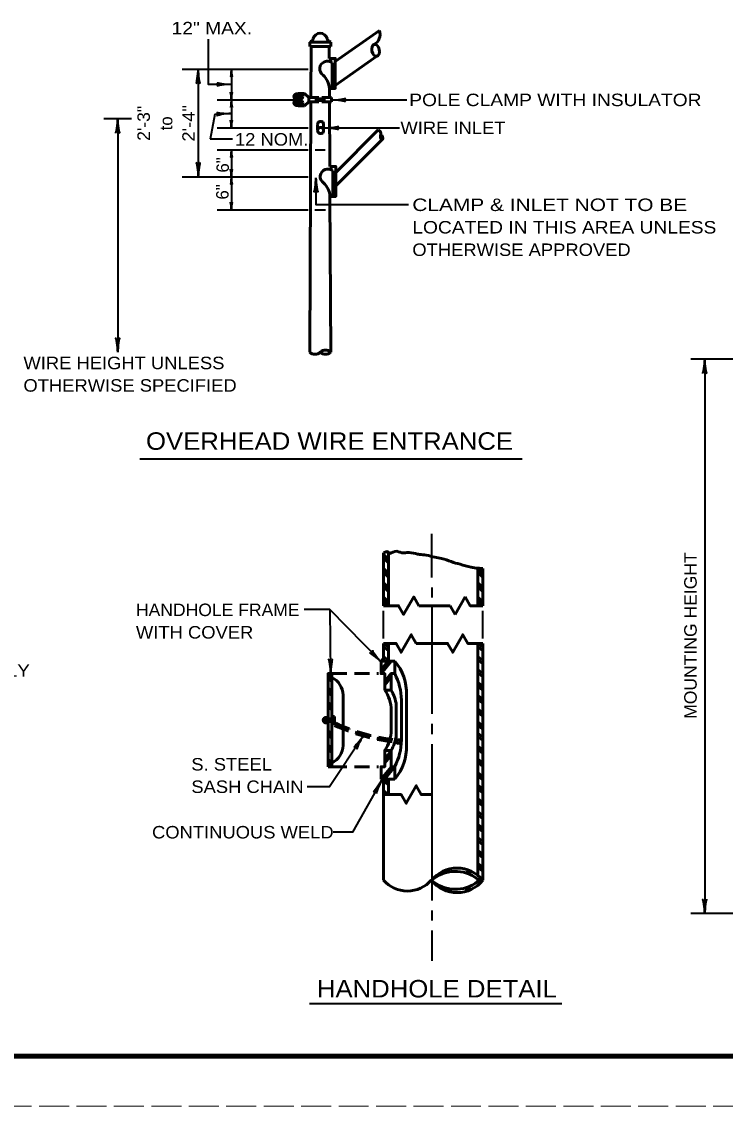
# Model space of a CAD drawing. Extents: x -1 to 679, y 1 to 441.
# Drawn here: x 219.9 to 360.8, y 0.8 to 218 of the extents above; entities that cross this region are included whole.
import ezdxf
from ezdxf.enums import TextEntityAlignment as Align

# ---------------------------------------------------------------- set-up
doc = ezdxf.new("R2010")
doc.units = 0
doc.linetypes.add('LONG_DASHED', pattern=[7.5, 6, -1.5])
doc.linetypes.add('MEDIUM_DASHED', pattern=[4.5, 3, -1.5])
doc.layers.add('1', color=7, linetype='Continuous', lineweight=13)
doc.layers.add('61', color=7, linetype='Continuous', lineweight=35)

msp = doc.modelspace()

# ---------------------------------------------------------------- hatches: boundary and pattern name
at = {"layer": '1'}
h = msp.add_hatch(color=256, dxfattribs=at)
edge = h.paths.add_edge_path()
edge.add_ellipse((275.324, 202.986), major_axis=(0.9, 0), ratio=0.6666667, start_angle=0, end_angle=360)
h = msp.add_hatch(color=256, dxfattribs=at)
edge = h.paths.add_edge_path()
edge.add_ellipse((275.324, 201.743), major_axis=(0.9, 0), ratio=0.6666667, start_angle=0, end_angle=360)
msp.add_hatch(color=256, dxfattribs=at).paths.add_polyline_path([(281.383, 78.137, 1), (280.293, 78.137, 1)])

# ---------------------------------------------------------------- linework, layer by layer
at = {"layer": '1', "lineweight": 53}
for p, q in [((282.705, 210.014), (291.552, 216.209)), ((277.594, 213.914), (281.794, 213.914)), ((277.594, 213.914), (277.594, 213.014)), ((277.594, 213.014), (281.794, 213.014)), ((277.894, 213.014), (277.844, 202.814)), ((281.494, 213.014), (281.505, 210.614)), ((281.794, 213.914), (281.794, 213.014)), ((282.705, 205.214), (291.061, 211.065)), ((281.805, 210.614), (281.805, 209.915)), ((282.105, 209.714), (282.105, 204.614)), ((281.535, 204.614), (281.543, 202.814)), ((276.524, 203.585), (275.324, 203.585)), ((277.444, 202.814), (276.524, 203.585)), ((277.444, 202.814), (279.394, 202.814)), ((277.444, 202.814), (277.444, 201.914)), ((278.914, 202.814), (278.914, 201.914)), ((279.394, 202.814), (279.394, 201.914)), ((279.994, 202.814), (281.944, 202.814)), ((279.994, 202.814), (279.994, 201.914)), ((280.474, 202.814), (280.474, 201.914)), ((281.944, 202.814), (281.944, 201.914)), ((276.524, 201.143), (275.324, 201.143)), ((277.444, 201.914), (276.524, 201.143)), ((277.444, 201.914), (279.394, 201.914)), ((277.839, 201.914), (277.594, 151.814)), ((279.994, 201.914), (281.944, 201.914)), ((281.548, 201.914), (281.611, 189.014)), ((279.17, 197.402), (279.176, 196.202)), ((280.37, 197.408), (280.376, 196.208)), ((282.811, 187.814), (291.297, 196.3)), ((282.811, 185.114), (292.145, 194.448)), ((281.911, 189.014), (281.911, 188.315)), ((282.211, 188.114), (282.211, 183.014)), ((281.641, 183.014), (281.794, 151.814)), ((292.372, 101.052), (292.372, 111.652)), ((293.372, 110.332), (292.372, 111.332)), ((293.372, 101.052), (293.372, 111.652)), ((293.372, 109.612), (292.372, 110.612)), ((293.372, 107.472), (292.372, 108.472)), ((293.372, 106.752), (292.372, 107.772)), ((311.272, 101.052), (311.272, 108.472)), ((312.272, 107.472), (311.272, 108.472)), ((312.272, 106.752), (311.272, 107.772)), ((312.272, 101.052), (312.272, 108.472)), ((293.372, 104.632), (292.372, 105.632)), ((293.372, 103.912), (292.372, 104.912)), ((312.272, 104.632), (311.272, 105.632)), ((312.272, 103.912), (311.272, 104.912)), ((293.372, 101.772), (292.372, 102.772)), ((293.372, 101.052), (292.372, 102.072)), ((308.752, 102.812), (306.732, 99.312)), ((312.272, 101.772), (311.272, 102.772)), ((312.272, 101.052), (311.272, 102.072)), ((299.432, 101.052), (305.732, 101.052)), ((306.732, 99.312), (305.732, 101.052)), ((292.372, 93.492), (293.372, 92.672)), ((292.372, 93.492), (292.372, 89.972)), ((293.372, 93.492), (293.372, 89.972)), ((311.272, 93.492), (312.272, 92.672)), ((312.272, 93.492), (312.272, 46.132)), ((292.372, 92.852), (293.372, 92.012)), ((311.272, 92.852), (312.272, 92.012)), ((293.872, 89.972), (291.872, 87.452)), ((293.232, 89.972), (291.872, 88.252)), ((291.872, 89.972), (293.872, 89.972)), ((292.372, 90.892), (293.372, 90.052)), ((292.372, 90.232), (292.692, 89.972)), ((294.632, 89.972), (292.612, 89.972)), ((311.272, 90.892), (312.272, 90.052)), ((311.272, 90.232), (312.272, 89.412)), ((282.032, 86.612), (281.272, 87.372)), ((282.032, 68.812), (282.032, 87.452)), ((293.872, 87.552), (292.612, 85.972)), ((311.272, 88.272), (312.272, 87.452)), ((311.272, 87.612), (312.272, 86.792)), ((282.032, 85.912), (281.272, 86.672)), ((293.872, 86.752), (292.612, 85.172)), ((311.272, 85.652), (312.272, 84.832)), ((311.272, 85.012), (312.272, 84.172)), ((282.032, 83.772), (281.272, 84.532)), ((282.032, 83.052), (281.272, 83.812)), ((284.312, 83.172), (284.312, 73.092)), ((293.872, 84.172), (292.612, 84.172)), ((296.952, 73.092), (296.952, 83.172)), ((311.272, 83.052), (312.272, 82.212)), ((282.032, 80.912), (281.272, 81.672)), ((282.032, 80.212), (281.272, 80.972)), ((294.932, 75.112), (294.932, 81.152)), ((295.952, 74.092), (295.952, 82.152)), ((311.272, 82.392), (312.272, 81.572)), ((311.272, 80.432), (312.272, 79.612)), ((282.032, 78.372), (281.272, 78.372)), ((282.032, 78.252), (281.272, 78.252)), ((282.532, 78.892), (282.032, 78.892)), ((282.152, 78.892), (282.152, 77.372)), ((282.232, 78.892), (282.232, 77.372)), ((282.232, 78.892), (282.232, 77.372)), ((282.312, 78.892), (282.312, 77.372)), ((282.312, 78.892), (282.312, 77.372)), ((282.372, 78.892), (282.372, 77.372)), ((282.432, 78.892), (282.432, 77.372)), ((282.452, 78.892), (282.452, 77.372)), ((282.492, 78.892), (282.492, 77.372)), ((282.532, 78.892), (282.532, 77.372)), ((293.932, 76.112), (293.932, 80.152)), ((311.272, 79.792), (312.272, 78.952)), ((282.032, 78.172), (281.272, 78.172)), ((282.032, 78.172), (281.272, 78.172)), ((282.032, 78.052), (281.272, 78.052)), ((282.032, 77.932), (281.272, 77.932)), ((282.032, 77.872), (281.272, 77.872)), ((282.532, 77.372), (282.032, 77.372)), ((311.272, 77.832), (312.272, 76.992)), ((311.272, 77.172), (312.272, 76.332)), ((282.032, 75.212), (281.272, 75.972)), ((282.032, 74.512), (281.272, 75.252)), ((311.272, 75.532), (312.272, 74.712)), ((311.272, 74.892), (312.272, 74.052)), ((282.032, 72.372), (281.272, 73.132)), ((282.032, 71.652), (281.272, 72.412)), ((293.872, 71.952), (292.612, 70.372)), ((311.272, 72.932), (312.272, 72.092)), ((311.272, 72.272), (312.272, 71.452)), ((282.032, 69.512), (281.272, 70.272)), ((282.032, 68.812), (281.272, 69.552)), ((293.872, 71.132), (292.612, 69.572)), ((311.272, 70.312), (312.272, 69.492)), ((311.272, 69.652), (312.272, 68.832)), ((282.032, 68.812), (281.272, 68.812)), ((293.952, 68.812), (291.932, 66.292)), ((294.632, 68.852), (292.572, 66.292)), ((311.272, 67.692), (312.272, 66.872)), ((291.872, 66.292), (293.872, 66.292)), ((292.372, 66.292), (292.372, 63.252)), ((292.372, 66.032), (293.372, 65.192)), ((294.632, 66.292), (292.612, 66.292)), ((292.852, 66.292), (293.372, 65.852)), ((293.372, 66.292), (293.372, 63.252)), ((311.272, 67.052), (312.272, 66.212)), ((292.372, 64.072), (293.352, 63.252)), ((292.372, 63.412), (292.552, 63.252)), ((311.272, 65.092), (312.272, 64.252)), ((311.272, 64.432), (312.272, 63.612)), ((311.272, 62.472), (312.272, 61.652)), ((311.272, 61.832), (312.272, 60.992)), ((311.272, 59.872), (312.272, 59.032)), ((311.272, 59.212), (312.272, 58.372)), ((311.272, 57.252), (312.272, 56.412)), ((311.272, 56.592), (312.272, 55.772)), ((311.272, 54.632), (312.272, 53.812)), ((311.272, 53.992), (312.272, 53.152)), ((311.272, 52.032), (312.272, 51.192)), ((311.272, 51.372), (312.272, 50.552)), ((304.732, 48.072), (304.932, 47.632)), ((305.212, 48.232), (305.432, 47.732)), ((309.312, 48.132), (309.012, 47.492)), ((309.772, 47.952), (309.492, 47.312)), ((311.272, 49.412), (312.272, 48.592)), ((311.272, 48.752), (312.272, 47.932)), ((310.972, 45.652), (312.152, 45.972)), ((311.272, 46.252), (311.912, 46.432)), ((304.912, 43.992), (305.132, 44.452)), ((305.392, 43.852), (305.632, 44.372)), ((309.132, 43.932), (308.832, 44.592)), ((309.612, 44.112), (309.312, 44.752))]:
    msp.add_line(p, q, dxfattribs=at)
at = {"layer": '1', "lineweight": 35}
for p, q in [((252.054, 208.483), (277.272, 208.483)), ((255.256, 208.483), (255.256, 186.92)), ((259.054, 202.352), (274.389, 202.352)), ((281.944, 202.334), (297.022, 202.334)), ((241.889, 198.562), (236.389, 198.562)), ((239.139, 198.562), (239.139, 151.814)), ((258.577, 199.455), (257.684, 194.482)), ((258.577, 199.455), (261.816, 199.613)), ((259.054, 196.75), (277.272, 196.75)), ((280.509, 196.72), (295.587, 196.72)), ((262.119, 194.482), (257.684, 194.482)), ((259.054, 192.311), (277.272, 192.311)), ((278.692, 192.314), (280.695, 192.314)), ((252.054, 186.92), (277.272, 186.92)), ((259.054, 180.312), (277.272, 180.312)), ((278.633, 180.314), (280.754, 180.314)), ((372.357, 150.421), (353.908, 150.421)), ((356.689, 150.421), (356.689, 39.421)), ((302.072, 106.692), (302.072, 115.432)), ((302.072, 104.692), (302.072, 102.672)), ((281.628, 100.328), (276.504, 100.328)), ((292.372, 94.512), (292.372, 100.052)), ((302.072, 101.052), (302.072, 97.292)), ((302.072, 100.652), (302.072, 79.392)), ((312.272, 94.512), (312.272, 100.052)), ((302.072, 77.372), (302.072, 75.352)), ((302.072, 73.332), (302.072, 42.052)), ((302.072, 40.032), (302.072, 38.012)), ((372.357, 39.421), (353.908, 39.421)), ((302.072, 36.012), (302.072, 29.972))]:
    msp.add_line(p, q, dxfattribs=at)
at = {"layer": '1', "lineweight": 40}
for p, q in [((243.596, 130.453), (320.124, 130.453)), ((277.557, 21.378), (328.11, 21.378))]:
    msp.add_line(p, q, dxfattribs=at)
at = {"layer": '1', "linetype": 'MEDIUM_DASHED', "lineweight": 53}
for p, q in [((282.032, 87.452), (291.352, 87.452)), ((282.032, 68.812), (291.352, 68.812))]:
    msp.add_line(p, q, dxfattribs=at)
at = {"layer": '1', "lineweight": 35}
for points in [[(261.854, 205.417), (257.318, 205.417), (257.318, 214.491)], [(261.916, 208.483), (261.916, 202.352), (261.916, 196.75)], [(261.916, 192.311), (261.916, 186.92), (261.916, 180.312)], [(278.837, 186.709), (278.837, 181.415), (297.384, 181.415)], [(291.872, 89.8), (281.628, 100.328), (281.782, 87.452)], [(288.311, 74.955), (281.544, 64.773), (277.072, 64.773)], [(292.015, 66.149), (286.186, 55.713), (282.28, 55.713)]]:
    msp.add_lwpolyline(points, dxfattribs=at)
at = {"layer": '1', "lineweight": 53}
for points in [[(281.505, 210.614), (282.705, 210.614), (282.705, 204.614), (281.535, 204.614)], [(281.611, 189.014), (282.811, 189.014), (282.811, 183.014), (281.641, 183.014)], [(292.372, 101.052), (295.392, 101.052), (296.392, 99.312), (298.412, 102.812), (299.432, 101.052)], [(312.272, 101.052), (309.752, 101.052), (308.752, 102.812)], [(292.372, 93.492), (294.892, 93.492), (295.892, 91.752), (297.912, 95.252), (298.912, 93.492)], [(312.272, 93.492), (309.252, 93.492), (308.252, 95.252), (306.232, 91.752), (305.212, 93.492), (298.912, 93.492)], [(311.272, 93.492), (311.272, 73.052), (311.272, 47.032)], [(292.612, 84.172), (292.612, 87.452), (291.872, 87.452), (291.872, 89.972)], [(292.612, 84.172), (293.872, 84.172), (293.872, 87.452), (294.632, 87.452), (294.632, 89.972)], [(281.272, 68.812), (281.272, 87.452), (282.032, 87.452)], [(293.872, 72.072), (292.612, 72.072), (292.612, 68.812), (291.872, 68.812), (291.872, 66.292)], [(292.612, 72.072), (293.872, 72.072), (293.872, 68.812), (294.632, 68.812), (294.632, 66.292)], [(301.952, 63.252), (299.932, 63.252), (298.912, 65.012), (296.912, 61.512), (295.892, 63.252), (292.372, 63.252), (292.372, 46.132)]]:
    msp.add_lwpolyline(points, dxfattribs=at)
for points in [[(291.872, 89.972), (292.372, 90.472), (292.372, 89.972)], [(291.872, 66.292), (292.372, 65.792), (292.372, 66.292)]]:
    msp.add_lwpolyline(points, close=True, dxfattribs=at)
for centre, radius in [((280.838, 78.137), 0.545), ((295.359, 73.854), 0.378)]:
    msp.add_circle(centre, radius, dxfattribs=at)
for centre, radius, start, end in [((279.694, 214.226), 1.442, 16.19781, 163.80219), ((289.443, 215.437), 2.246, 295.32486, 20.09191), ((277.402, 214.822), 0.928, 281.94387, 347.91984), ((281.986, 214.822), 0.928, 192.08016, 258.05613), ((281.114, 208.558), 1.523, 49.39069, 236.15933), ((277.59, 204.387), 3.951, 3.29768, 47.3671), ((279.77, 197.42), 0.6, 358.85054, 181.71286), ((279.776, 196.22), 0.6, 358.85054, 181.71286), ((279.776, 196.184), 0.6, 178.28714, 1.14946), ((291.012, 195.509), 0.84, 339.80476, 70.23541), ((281.22, 186.958), 1.523, 49.39069, 236.15933), ((277.696, 182.787), 3.951, 3.29768, 47.3671), ((280.744, 150.722), 1.515, 46.13132, 133.86867), ((278.644, 152.907), 1.515, 226.13132, 313.86868), ((280.744, 152.907), 1.515, 226.13132, 313.86868), ((287.236, 83.654), 9.729, 357.13004, 40.48815), ((284.139, 82.045), 11.806, 0.54939, 27.24732), ((280.2, 83.021), 4.106, 2.02606, 63.44439), ((286.947, 80.104), 6.982, 0.31998, 35.66459), ((287.801, 80.352), 7.18, 6.38376, 32.16514), ((286.947, 76.15), 6.982, 324.33541, 359.68002), ((287.801, 75.901), 7.18, 327.83486, 353.61624), ((284.139, 74.243), 11.806, 332.75268, 359.45061), ((280.2, 73.232), 4.106, 296.55561, 357.97394), ((287.236, 72.635), 9.729, 319.51185, 2.86996), ((306.751, 40.681), 7.178, 51.54154, 132.04732), ((307.109, 41.942), 6.576, 38.8447, 141.1553), ((297.155, 50.243), 6.317, 220.71167, 319.28832), ((307.109, 50.191), 6.576, 218.22248, 321.77751), ((306.751, 51.453), 7.178, 227.95268, 308.4983), ((311.038, 46.068), 0.294, 307.8273, 52.77092)]:
    msp.add_arc(centre, radius, start, end, dxfattribs=at)
at = {"layer": '1', "linetype": 'MEDIUM_DASHED', "lineweight": 53}
for centre, radius, start, end in [((299.23, 113.296), 39.613, 245.08086, 263.60629), ((298.714, 111.75), 38.237, 245.04728, 263.19799), ((298.378, 110.55), 36.501, 244.77769, 263.49597)]:
    msp.add_arc(centre, radius, start, end, dxfattribs=at)
at = {"layer": '1', "lineweight": 53}
for centre, major_axis, ratio in [((290.793, 212.251), (-0.268, 1.186), 0.618585), ((275.324, 202.986), (0.9, 0), 0.666667), ((275.324, 201.743), (0.9, 0), 0.666667), ((291.986, 194.838), (-0.159, 0.39), 0.505648)]:
    msp.add_ellipse(centre, major_axis=major_axis, ratio=ratio, dxfattribs=at)
at = {"layer": '1', "lineweight": 40}
for centre, major_axis, ratio, start_param, end_param in [((255.044, 207.353), (0.176, 1.756), 0.07063, 3.1407148, 5.41811), ((255.532, 207.383), (-0.156, 1.786), 0.122415, 0.8963533, 3.1415927), ((261.708, 207.353), (0.176, 1.756), 0.07063, 4.7093373, 5.41811), ((262.196, 207.382), (-0.156, 1.786), 0.122415, 0.8963533, 1.5837952), ((261.888, 208.7), (0.176, 1.756), 0.07063, 3.1407148, 3.8293255), ((262, 208.72), (-0.156, 1.786), 0.122415, 2.4431075, 3.1415927), ((260.763, 205.14), (1.786, 0.156), 0.122415, 0.8963533, 3.1415927), ((260.734, 205.628), (1.756, -0.176), 0.07063, 3.1407148, 5.41811), ((261.877, 202.134), (0.176, -1.756), 0.07063, 2.4538598, 3.1424706), ((261.696, 203.482), (0.176, -1.756), 0.07063, 0.8650754, 1.573848), ((261.708, 201.222), (0.176, 1.756), 0.07063, 4.7093373, 5.41811), ((262.184, 203.452), (-0.156, -1.786), 0.122415, 4.6993901, 5.386832), ((262.196, 201.252), (-0.156, 1.786), 0.122415, 0.8963533, 1.5837952), ((261.989, 202.115), (-0.156, -1.786), 0.122415, 3.1415927, 3.8400778), ((283.073, 202.114), (-1.756, 0.176), 0.07063, 3.1407148, 5.41811), ((283.044, 202.602), (-1.786, -0.156), 0.122415, 0.8963533, 3.1415927), ((260.686, 199.77), (1.763, -0.09), 0.07063, 3.1407148, 5.41811), ((261.888, 202.57), (0.176, 1.756), 0.07063, 3.1407148, 3.8293255), ((262, 202.589), (-0.156, 1.786), 0.122415, 2.4431075, 3.1415927), ((238.928, 197.442), (0.176, 1.756), 0.07063, 3.1407148, 5.41811), ((239.416, 197.471), (-0.156, 1.786), 0.122415, 0.8963533, 3.1415927), ((260.739, 199.284), (1.776, 0.243), 0.122415, 0.8963533, 3.1415927), ((261.877, 196.532), (0.176, -1.756), 0.07063, 2.4538598, 3.1424706), ((261.696, 197.88), (0.176, -1.756), 0.07063, 0.8650754, 1.573848), ((262.184, 197.85), (-0.156, -1.786), 0.122415, 4.6993901, 5.386832), ((261.989, 196.513), (-0.156, -1.786), 0.122415, 3.1415927, 3.8400778), ((281.638, 196.5), (-1.756, 0.176), 0.07063, 3.1407148, 5.41811), ((281.609, 196.988), (-1.786, -0.156), 0.122415, 0.8963533, 3.1415927), ((261.888, 192.528), (0.176, 1.756), 0.07063, 3.1407148, 3.8293255), ((261.708, 191.181), (0.176, 1.756), 0.07063, 4.7093373, 5.41811), ((262.196, 191.21), (-0.156, 1.786), 0.122415, 0.8963533, 1.5837952), ((262, 192.548), (-0.156, 1.786), 0.122415, 2.4431075, 3.1415927), ((254.988, 188.02), (0.156, -1.786), 0.122415, 0.8963533, 3.1415927), ((255.476, 188.049), (-0.176, -1.756), 0.07063, 3.1407148, 5.41811), ((261.877, 186.702), (0.176, -1.756), 0.07063, 2.4538598, 3.1424706), ((261.696, 188.049), (0.176, -1.756), 0.07063, 0.8650754, 1.573848), ((261.708, 185.79), (0.176, 1.756), 0.07063, 4.7093373, 5.41811), ((262.184, 188.02), (-0.156, -1.786), 0.122415, 4.6993901, 5.386832), ((262.196, 185.819), (-0.156, 1.786), 0.122415, 0.8963533, 1.5837952), ((261.989, 186.683), (-0.156, -1.786), 0.122415, 3.1415927, 3.8400778), ((261.888, 187.137), (0.176, 1.756), 0.07063, 3.1407148, 3.8293255), ((262, 187.157), (-0.156, 1.786), 0.122415, 2.4431075, 3.1415927), ((278.626, 185.588), (0.176, 1.756), 0.07063, 3.1407148, 5.41811), ((279.114, 185.618), (-0.156, 1.786), 0.122415, 0.8963533, 3.1415927), ((261.877, 180.095), (0.176, -1.756), 0.07063, 2.4538598, 3.1424706), ((261.696, 181.442), (0.176, -1.756), 0.07063, 0.8650754, 1.573848), ((262.184, 181.413), (-0.156, -1.786), 0.122415, 4.6993901, 5.386832), ((261.989, 180.075), (-0.156, -1.786), 0.122415, 3.1415927, 3.8400778), ((238.871, 152.914), (0.156, -1.786), 0.122415, 0.8963533, 3.1415927), ((239.359, 152.944), (-0.176, -1.756), 0.07063, 3.1407148, 5.41811), ((356.477, 149.3), (0.176, 1.756), 0.07063, 3.1407148, 5.41811), ((356.965, 149.33), (-0.156, 1.786), 0.122415, 0.8963533, 3.1415927), ((290.913, 90.389), (1.357, -1.171), 0.122415, 0.8963533, 3.1415927), ((290.913, 90.389), (1.357, -1.171), 0.122415, 0.8963533, 3.1415927), ((291.243, 90.751), (-1.099, 1.381), 0.07063, 6.2823074, 8.5597026), ((291.243, 90.751), (-1.099, 1.381), 0.07063, 6.2823074, 8.5597026), ((281.492, 88.54), (0.177, -1.784), 0.122415, 0.8963533, 3.1415927), ((281.492, 88.54), (0.177, -1.784), 0.122415, 0.8963533, 3.1415927), ((281.98, 88.575), (-0.155, -1.758), 0.07063, 3.1407148, 5.41811), ((281.98, 88.575), (-0.155, -1.758), 0.07063, 3.1407148, 5.41811), ((287.514, 74.139), (-1.118, -1.366), 0.07063, 6.2823074, 8.5597026), ((287.514, 74.139), (-1.118, -1.366), 0.07063, 6.2823074, 8.5597026), ((287.937, 73.893), (0.858, 1.574), 0.122415, 0.8963533, 3.1415927), ((287.937, 73.893), (0.858, 1.574), 0.122415, 0.8963533, 3.1415927), ((291.284, 65.274), (1.01, 1.448), 0.07063, 3.1407148, 5.41811), ((291.284, 65.274), (1.01, 1.448), 0.07063, 3.1407148, 5.41811), ((291.724, 65.062), (0.734, 1.635), 0.122415, 0.8963533, 3.1415927), ((291.724, 65.062), (0.734, 1.635), 0.122415, 0.8963533, 3.1415927), ((356.413, 40.512), (0.156, -1.786), 0.122415, 0.8963533, 3.1415927), ((356.901, 40.542), (-0.176, -1.756), 0.07063, 3.1407148, 5.41811)]:
    msp.add_ellipse(centre, major_axis=major_axis, ratio=ratio, start_param=start_param, end_param=end_param, dxfattribs=at)
at = {"layer": '1', "lineweight": 53}
for points in [[(292.372, 111.652), (292.792, 111.792), (293.232, 111.852), (293.372, 111.652), (294.652, 111.932), (296.032, 111.652), (297.032, 111.692), (298.792, 111.492), (299.592, 111.312), (300.912, 111.192), (302.672, 110.752), (304.012, 110.532), (305.912, 109.872), (307.692, 109.352), (309.912, 108.752), (311.272, 108.472)], [(310.892, 108.552), (311.752, 108.532), (312.272, 108.472)]]:
    msp.add_spline(points, degree=3, dxfattribs=at)
at = {"layer": '61', "lineweight": 158}
msp.add_line((668.452, 10.826), (29.392, 10.846), dxfattribs=at)
at = {"layer": '61', "linetype": 'LONG_DASHED', "lineweight": 13}
msp.add_line((679.392, 0.846), (-0.668, 0.826), dxfattribs=at)

# ---------------------------------------------------------------- texts
at = {"layer": '1'}
for s, height, width, p in [('12" MAX.', 2.5, 1.15, (249.944, 215.446)), ('POLE CLAMP WITH INSULATOR', 2.5, 1.15, (297.518, 201.074)), ('WIRE INLET', 2.5, 1.1, (295.762, 195.493)), ('12 NOM.', 2.5, 1.1, (262.623, 193.171)), ('CLAMP & INLET NOT TO BE', 2.5, 1.25, (298.14, 180.075)), ('LOCATED IN THIS AREA UNLESS', 2.5, 1.15, (298.14, 175.575)), ('OTHERWISE APPROVED', 2.5, 1.1, (298.14, 171.075)), ('WIRE HEIGHT UNLESS', 2.5, 1.1, (220.265, 148.407)), ('OTHERWISE SPECIFIED', 2.5, 1.1, (220.265, 143.907)), ('OVERHEAD WIRE ENTRANCE', 3.5, 1.1, (244.806, 132.268)), ('HANDHOLE FRAME', 2.5, 1.05, (242.796, 98.977)), ('WITH COVER', 2.5, 1.1, (242.796, 94.477)), ('3/16" x 2" HINGE ASSEMBLY', 2.5, 1.15, (170.13, 86.841)), ('S. STEEL', 2.5, 1.1, (253.886, 68.057)), ('SASH CHAIN', 2.5, 1.1, (253.886, 63.557)), ('CONTINUOUS WELD', 2.5, 1.1, (246.015, 54.453)), ('HANDHOLE DETAIL', 3.5, 1.1, (279.029, 22.623))]:
    msp.add_text(s, height=height, dxfattribs=dict(at, width=width)).set_placement(p)
for s, width, p in [('2\'-3"', 1.05, (245.583, 197.628)), ('2\'-4"', 1.1, (254.583, 197.628))]:
    msp.add_text(s, height=2.5, rotation=90, dxfattribs=dict(at, width=width)).set_placement(p, align=Align.CENTER)
msp.add_text('to', height=2.5, rotation=90, dxfattribs=at).set_placement((250.083, 197.628), align=Align.CENTER)
for p in [(261.416, 187.78), (261.355, 182.378)]:
    msp.add_text('6"', height=2.5, rotation=90, dxfattribs=at).set_placement(p)
at = {"layer": '1', "width": 1.05}
msp.add_text('MOUNTING HEIGHT', height=2.5, rotation=90, dxfattribs=at).set_placement((355.09, 78.401))

doc.saveas('drawing.dxf')
